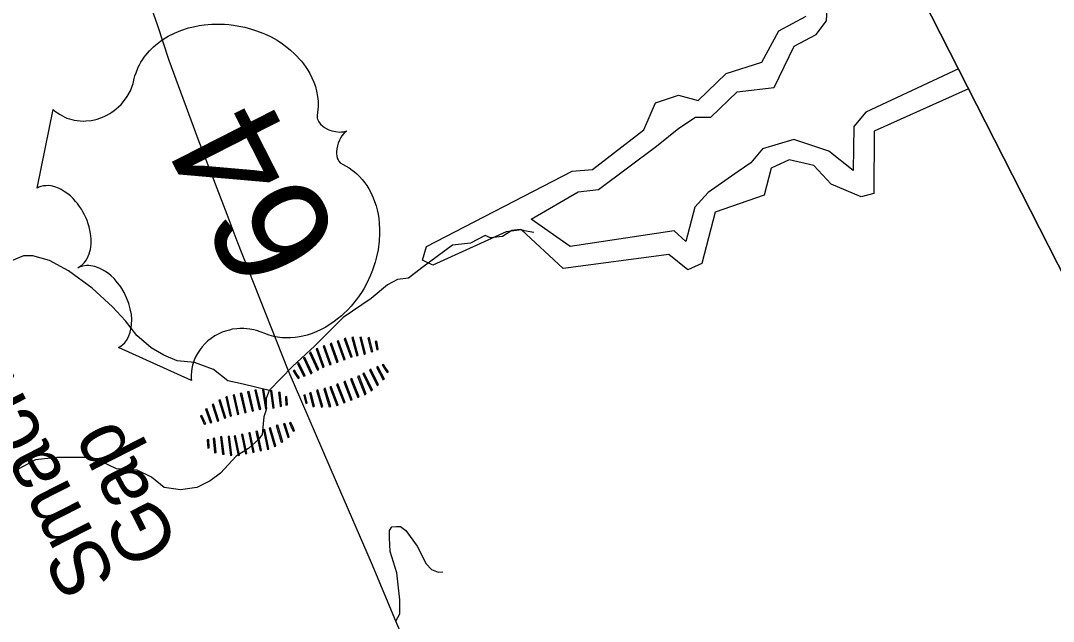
# Model space of a CAD drawing. Extents: x 558484 to 564063, y 513718 to 518374.
# Drawn here: x 559460.3 to 559521.9, y 515130.7 to 515166.6 of the extents above; entities that cross this region are included whole.
import ezdxf

# ---------------------------------------------------------------- set-up
doc = ezdxf.new("R2010")
doc.units = 0
doc.layers.add('Default', color=7, linetype='Continuous')

msp = doc.modelspace()

# ---------------------------------------------------------------- linework, layer by layer
at = {"layer": 'Default'}
for p, q in [((559470.585, 515166.219), (559470.927, 515166.283)), ((559470.927, 515166.283), (559471.228, 515166.33)), ((559471.228, 515166.33), (559471.685, 515166.371)), ((559471.685, 515166.371), (559472.029, 515166.376)), ((559472.029, 515166.376), (559472.441, 515166.365)), ((559472.441, 515166.365), (559472.697, 515166.345)), ((559472.697, 515166.345), (559472.976, 515166.311)), ((559472.976, 515166.311), (559473.306, 515166.258)), ((559469.073, 515165.643), (559469.458, 515165.841)), ((559469.458, 515165.841), (559469.839, 515165.998)), ((559469.839, 515165.998), (559470.301, 515166.146)), ((559470.301, 515166.146), (559470.585, 515166.219)), ((559473.306, 515166.258), (559473.665, 515166.184)), ((559473.665, 515166.184), (559474.06, 515166.076)), ((559474.06, 515166.076), (559474.36, 515165.978)), ((559474.36, 515165.978), (559474.724, 515165.837)), ((559474.724, 515165.837), (559474.934, 515165.746)), ((559474.934, 515165.746), (559475.218, 515165.608)), ((559468.197, 515165.008), (559468.322, 515165.122)), ((559468.322, 515165.122), (559468.618, 515165.35)), ((559468.618, 515165.35), (559468.767, 515165.456)), ((559468.767, 515165.456), (559469.073, 515165.643)), ((559475.218, 515165.608), (559475.578, 515165.405)), ((559475.578, 515165.405), (559475.908, 515165.191)), ((559475.908, 515165.191), (559476.171, 515165.001)), ((559467.645, 515164.393), (559467.737, 515164.519)), ((559467.737, 515164.519), (559467.963, 515164.781)), ((559467.963, 515164.781), (559468.197, 515165.008)), ((559476.171, 515165.001), (559476.385, 515164.823)), ((559476.385, 515164.823), (559476.647, 515164.585)), ((559476.647, 515164.585), (559477.033, 515164.162)), ((559467.297, 515163.803), (559467.368, 515163.946)), ((559467.368, 515163.946), (559467.452, 515164.097)), ((559467.452, 515164.097), (559467.544, 515164.242)), ((559467.544, 515164.242), (559467.645, 515164.393)), ((559477.033, 515164.162), (559477.162, 515164.003)), ((559477.162, 515164.003), (559477.302, 515163.806)), ((559477.302, 515163.806), (559477.422, 515163.618)), ((559467.056, 515163.117), (559467.098, 515163.279)), ((559467.098, 515163.279), (559467.161, 515163.472)), ((559467.161, 515163.472), (559467.297, 515163.803)), ((559477.422, 515163.618), (559477.532, 515163.431)), ((559477.532, 515163.431), (559477.664, 515163.171)), ((559466.822, 515162.39), (559466.916, 515162.614)), ((559466.916, 515162.614), (559466.988, 515162.824)), ((559466.988, 515162.824), (559467.056, 515163.117)), ((559477.664, 515163.171), (559477.776, 515162.904)), ((559477.776, 515162.904), (559477.865, 515162.642)), ((559477.865, 515162.642), (559477.941, 515162.361)), ((559466.415, 515161.745), (559466.626, 515162.044)), ((559466.626, 515162.044), (559466.822, 515162.39)), ((559477.941, 515162.361), (559477.997, 515162.056)), ((559477.997, 515162.056), (559478.025, 515161.766)), ((559465.979, 515161.305), (559466.118, 515161.428)), ((559466.118, 515161.428), (559466.273, 515161.581)), ((559466.273, 515161.581), (559466.415, 515161.745)), ((559478.029, 515161.462), (559477.98, 515160.917)), ((559478.025, 515161.766), (559478.029, 515161.462)), ((559461.259, 515156.585), (559462.216, 515161.265)), ((559462.216, 515161.265), (559462.286, 515161.202)), ((559462.286, 515161.202), (559462.467, 515161.066)), ((559462.467, 515161.066), (559462.625, 515160.965)), ((559462.625, 515160.965), (559462.903, 515160.818)), ((559462.903, 515160.818), (559463.041, 515160.765)), ((559463.041, 515160.765), (559463.184, 515160.714)), ((559464.845, 515160.701), (559465.163, 515160.813)), ((559465.163, 515160.813), (559465.309, 515160.875)), ((559465.309, 515160.875), (559465.449, 515160.946)), ((559465.449, 515160.946), (559465.592, 515161.029)), ((559465.592, 515161.029), (559465.727, 515161.115)), ((559465.727, 515161.115), (559465.862, 515161.216)), ((559465.862, 515161.216), (559465.979, 515161.305)), ((559477.98, 515160.917), (559477.977, 515160.766)), ((559477.977, 515160.766), (559477.993, 515160.691)), ((559463.184, 515160.714), (559463.328, 515160.674)), ((559463.328, 515160.674), (559463.461, 515160.641)), ((559463.461, 515160.641), (559463.644, 515160.613)), ((559463.644, 515160.613), (559463.822, 515160.594)), ((559463.822, 515160.594), (559464.012, 515160.585)), ((559464.012, 515160.585), (559464.172, 515160.588)), ((559464.172, 515160.588), (559464.492, 515160.622)), ((559464.492, 515160.622), (559464.686, 515160.659)), ((559464.686, 515160.659), (559464.845, 515160.701)), ((559477.993, 515160.691), (559478.067, 515160.527)), ((559478.067, 515160.527), (559478.174, 515160.394)), ((559478.174, 515160.394), (559478.313, 515160.271)), ((559478.313, 515160.271), (559478.41, 515160.204)), ((559478.41, 515160.204), (559478.553, 515160.122)), ((559478.553, 515160.122), (559478.676, 515160.066)), ((559478.676, 515160.066), (559478.842, 515160.007)), ((559478.842, 515160.007), (559478.973, 515159.974)), ((559478.973, 515159.974), (559479.074, 515159.95)), ((559479.074, 515159.95), (559479.316, 515159.928)), ((559479.372, 515159.57), (559479.305, 515159.443)), ((559479.316, 515159.928), (559479.423, 515159.93)), ((559479.454, 515159.701), (559479.372, 515159.57)), ((559479.423, 515159.93), (559479.558, 515159.944)), ((559479.56, 515159.832), (559479.454, 515159.701)), ((559479.558, 515159.944), (559479.742, 515159.99)), ((559479.742, 515159.99), (559479.56, 515159.832)), ((559479.145, 515158.926), (559479.132, 515158.751)), ((559479.183, 515159.104), (559479.145, 515158.926)), ((559479.23, 515159.259), (559479.183, 515159.104)), ((559479.305, 515159.443), (559479.23, 515159.259)), ((559479.132, 515158.751), (559479.132, 515158.616)), ((559479.132, 515158.616), (559479.144, 515158.498)), ((559479.144, 515158.498), (559479.176, 515158.363)), ((559479.176, 515158.363), (559479.218, 515158.261)), ((559479.218, 515158.261), (559479.261, 515158.181)), ((559479.261, 515158.181), (559479.343, 515158.083)), ((559479.343, 515158.083), (559479.528, 515157.988)), ((559479.528, 515157.988), (559479.699, 515157.895)), ((559479.699, 515157.895), (559479.875, 515157.789)), ((559479.875, 515157.789), (559480.067, 515157.654)), ((559480.067, 515157.654), (559480.199, 515157.551)), ((559480.199, 515157.551), (559480.344, 515157.422)), ((559480.344, 515157.422), (559480.503, 515157.265)), ((559480.503, 515157.265), (559480.66, 515157.087)), ((559480.66, 515157.087), (559480.809, 515156.898)), ((559461.36, 515156.632), (559461.259, 515156.585)), ((559461.484, 515156.675), (559461.36, 515156.632)), ((559461.634, 515156.711), (559461.484, 515156.675)), ((559461.787, 515156.722), (559461.634, 515156.711)), ((559461.936, 515156.726), (559461.787, 515156.722)), ((559462.093, 515156.705), (559461.936, 515156.726)), ((559462.323, 515156.648), (559462.093, 515156.705)), ((559462.531, 515156.571), (559462.323, 515156.648)), ((559462.691, 515156.499), (559462.531, 515156.571)), ((559462.881, 515156.385), (559462.691, 515156.499)), ((559480.809, 515156.898), (559480.932, 515156.728)), ((559480.932, 515156.728), (559481.051, 515156.539)), ((559481.051, 515156.539), (559481.148, 515156.363)), ((559463.094, 515156.233), (559462.881, 515156.385)), ((559463.244, 515156.109), (559463.094, 515156.233)), ((559463.401, 515155.961), (559463.244, 515156.109)), ((559463.556, 515155.788), (559463.401, 515155.961)), ((559481.148, 515156.363), (559481.241, 515156.175)), ((559481.241, 515156.175), (559481.317, 515155.993)), ((559481.317, 515155.993), (559481.402, 515155.781)), ((559463.667, 515155.653), (559463.556, 515155.788)), ((559463.794, 515155.481), (559463.667, 515155.653)), ((559463.901, 515155.32), (559463.794, 515155.481)), ((559463.996, 515155.157), (559463.901, 515155.32)), ((559481.402, 515155.781), (559481.493, 515155.511)), ((559481.493, 515155.511), (559481.552, 515155.278)), ((559481.552, 515155.278), (559481.605, 515155.028)), ((559464.09, 515154.977), (559463.996, 515155.157)), ((559464.161, 515154.828), (559464.09, 515154.977)), ((559464.24, 515154.64), (559464.161, 515154.828)), ((559464.304, 515154.45), (559464.24, 515154.64)), ((559481.605, 515155.028), (559481.649, 515154.766)), ((559481.649, 515154.766), (559481.68, 515154.477)), ((559464.363, 515154.262), (559464.304, 515154.45)), ((559464.411, 515154.066), (559464.363, 515154.262)), ((559464.445, 515153.871), (559464.411, 515154.066)), ((559481.68, 515154.477), (559481.702, 515154.107)), ((559481.702, 515154.107), (559481.701, 515153.841)), ((559464.466, 515153.713), (559464.445, 515153.871)), ((559464.475, 515153.554), (559464.466, 515153.713)), ((559464.476, 515153.222), (559464.475, 515153.554)), ((559481.68, 515153.412), (559481.608, 515152.885)), ((559481.701, 515153.841), (559481.68, 515153.412)), ((559464.371, 515152.66), (559464.41, 515152.797)), ((559464.41, 515152.797), (559464.436, 515152.916)), ((559464.436, 515152.916), (559464.476, 515153.222)), ((559481.608, 515152.885), (559481.52, 515152.47)), ((559464.007, 515152.051), (559464.087, 515152.141)), ((559464.087, 515152.141), (559464.193, 515152.284)), ((559464.193, 515152.284), (559464.271, 515152.423)), ((559464.271, 515152.423), (559464.371, 515152.66)), ((559481.435, 515152.155), (559481.273, 515151.675)), ((559481.52, 515152.47), (559481.435, 515152.155)), ((559463.688, 515151.822), (559463.837, 515151.912)), ((559463.88, 515151.902), (559463.688, 515151.822)), ((559463.837, 515151.912), (559463.926, 515151.977)), ((559463.978, 515151.927), (559463.88, 515151.902)), ((559463.926, 515151.977), (559464.007, 515152.051)), ((559464.215, 515151.959), (559463.978, 515151.927)), ((559464.335, 515151.956), (559464.215, 515151.959)), ((559464.463, 515151.947), (559464.335, 515151.956)), ((559464.71, 515151.896), (559464.463, 515151.947)), ((559464.969, 515151.805), (559464.71, 515151.896)), ((559465.124, 515151.726), (559464.969, 515151.805)), ((559465.307, 515151.619), (559465.124, 515151.726)), ((559465.514, 515151.475), (559465.307, 515151.619)), ((559481.273, 515151.675), (559481.157, 515151.381)), ((559465.681, 515151.332), (559465.514, 515151.475)), ((559465.847, 515151.171), (559465.681, 515151.332)), ((559465.982, 515151.019), (559465.847, 515151.171)), ((559466.247, 515150.679), (559465.982, 515151.019)), ((559480.928, 515150.897), (559480.75, 515150.571)), ((559481.157, 515151.381), (559480.928, 515150.897)), ((559466.446, 515150.349), (559466.247, 515150.679)), ((559466.602, 515150.03), (559466.446, 515150.349)), ((559480.611, 515150.348), (559480.378, 515150.007)), ((559480.75, 515150.571), (559480.611, 515150.348)), ((559466.729, 515149.691), (559466.602, 515150.03)), ((559466.82, 515149.368), (559466.729, 515149.691)), ((559480.225, 515149.806), (559479.994, 515149.53)), ((559480.378, 515150.007), (559480.225, 515149.806)), ((559466.883, 515149.039), (559466.82, 515149.368)), ((559466.906, 515148.726), (559466.883, 515149.039)), ((559479.561, 515149.081), (559479.421, 515148.953)), ((559479.775, 515149.294), (559479.561, 515149.081)), ((559479.994, 515149.53), (559479.775, 515149.294)), ((559466.881, 515148.259), (559466.9, 515148.437)), ((559466.9, 515148.437), (559466.906, 515148.726)), ((559478.726, 515148.425), (559478.443, 515148.255)), ((559478.984, 515148.604), (559478.726, 515148.425)), ((559479.167, 515148.745), (559478.984, 515148.604)), ((559479.421, 515148.953), (559479.167, 515148.745)), ((559466.722, 515147.706), (559466.819, 515147.978)), ((559466.819, 515147.978), (559466.881, 515148.259)), ((559472.061, 515147.856), (559471.868, 515147.75)), ((559472.304, 515147.968), (559472.061, 515147.856)), ((559472.508, 515148.039), (559472.304, 515147.968)), ((559472.731, 515148.103), (559472.508, 515148.039)), ((559472.908, 515148.145), (559472.731, 515148.103)), ((559473.171, 515148.182), (559472.908, 515148.145)), ((559473.348, 515148.196), (559473.171, 515148.182)), ((559473.594, 515148.193), (559473.348, 515148.196)), ((559473.765, 515148.184), (559473.594, 515148.193)), ((559473.962, 515148.163), (559473.765, 515148.184)), ((559474.183, 515148.123), (559473.962, 515148.163)), ((559474.348, 515148.081), (559474.183, 515148.123)), ((559474.635, 515147.984), (559474.348, 515148.081)), ((559474.849, 515147.889), (559474.635, 515147.984)), ((559475.108, 515147.798), (559474.849, 515147.889)), ((559475.38, 515147.722), (559475.108, 515147.798)), ((559477.373, 515147.802), (559477.108, 515147.734)), ((559477.673, 515147.899), (559477.373, 515147.802)), ((559477.948, 515148.007), (559477.673, 515147.899)), ((559478.176, 515148.114), (559477.948, 515148.007)), ((559478.443, 515148.255), (559478.176, 515148.114)), ((559466.255, 515147.139), (559466.401, 515147.256)), ((559466.401, 515147.256), (559466.473, 515147.325)), ((559466.473, 515147.325), (559466.595, 515147.483)), ((559466.595, 515147.483), (559466.722, 515147.706)), ((559471.286, 515147.302), (559471.107, 515147.107)), ((559471.452, 515147.452), (559471.286, 515147.302)), ((559471.65, 515147.607), (559471.452, 515147.452)), ((559471.868, 515147.75), (559471.65, 515147.607)), ((559475.613, 515147.677), (559475.38, 515147.722)), ((559475.877, 515147.646), (559475.613, 515147.677)), ((559476.114, 515147.634), (559475.877, 515147.646)), ((559476.39, 515147.636), (559476.114, 515147.634)), ((559476.668, 515147.66), (559476.39, 515147.636)), ((559476.912, 515147.695), (559476.668, 515147.66)), ((559477.108, 515147.734), (559476.912, 515147.695)), ((559466.121, 515147.061), (559466.255, 515147.139)), ((559470.469, 515145.081), (559466.121, 515147.061)), ((559470.831, 515146.71), (559470.701, 515146.465)), ((559470.985, 515146.949), (559470.831, 515146.71)), ((559471.107, 515147.107), (559470.985, 515146.949)), ((559470.538, 515146.012), (559470.5, 515145.814)), ((559470.61, 515146.235), (559470.538, 515146.012)), ((559470.701, 515146.465), (559470.61, 515146.235)), ((559470.472, 515145.631), (559470.456, 515145.409)), ((559470.456, 515145.409), (559470.458, 515145.205)), ((559470.5, 515145.814), (559470.472, 515145.631)), ((559470.458, 515145.205), (559470.469, 515145.081))]:
    msp.add_line(p, q, dxfattribs=at)
for points in [[(559691.675, 514819.143), (559493.11, 515209.152), (559540.175, 515233.114), (559738.739, 514843.105)], [(559363.742, 514652.183), (559165.177, 515042.192), (559493.11, 515209.152), (559691.675, 514819.143)], [(559363.742, 514652.183), (559165.177, 515042.192), (559493.11, 515209.152), (559691.675, 514819.143)], [(559479.146, 515146.169), (559479.229, 515146.199), (559478.827, 515147.31), (559478.745, 515147.28)], [(559479.57, 515146.323), (559479.653, 515146.352), (559479.251, 515147.463), (559479.169, 515147.434)], [(559479.985, 515146.473), (559480.07, 515146.503), (559479.668, 515147.614), (559479.584, 515147.584)], [(559480.338, 515146.561), (559480.421, 515146.591), (559480.122, 515147.684), (559480.037, 515147.653)], [(559480.781, 515146.643), (559480.864, 515146.673), (559480.593, 515147.681), (559480.51, 515147.651)], [(559481.094, 515147.62), (559481.082, 515147.654), (559480.998, 515147.624), (559481.192, 515146.831), (559481.204, 515146.796), (559481.287, 515146.826)], [(559481.537, 515146.916), (559481.619, 515146.946), (559481.526, 515147.445), (559481.444, 515147.416)], [(559477.985, 515145.711), (559478.067, 515145.741), (559477.601, 515146.773), (559477.519, 515146.743)], [(559478.305, 515145.866), (559478.39, 515145.896), (559477.989, 515147.007), (559477.904, 515146.977)], [(559478.729, 515146.019), (559478.813, 515146.049), (559478.412, 515147.16), (559478.328, 515147.13)], [(559476.894, 515146.103), (559476.882, 515146.137), (559476.798, 515146.107), (559477.158, 515145.373), (559477.17, 515145.339), (559477.254, 515145.369)], [(559477.587, 515145.489), (559477.669, 515145.519), (559477.233, 515146.467), (559477.15, 515146.437)], [(559481.929, 515146.053), (559481.847, 515146.021), (559481.997, 515145.797), (559482.15, 515145.569), (559482.232, 515145.601), (559482.08, 515145.829)], [(559476.83, 515145.216), (559476.913, 515145.246), (559476.768, 515145.474), (559476.621, 515145.705), (559476.538, 515145.676), (559476.684, 515145.444)], [(559480.47, 515145.369), (559480.386, 515145.336), (559480.813, 515144.235), (559480.898, 515144.268)], [(559480.787, 515145.531), (559480.705, 515145.499), (559481.195, 515144.478), (559481.277, 515144.51)], [(559481.179, 515145.762), (559481.097, 515145.73), (559481.556, 515144.793), (559481.638, 515144.825)], [(559481.886, 515145.165), (559481.899, 515145.131), (559481.982, 515145.164), (559481.605, 515145.888), (559481.592, 515145.922), (559481.509, 515145.89)], [(559478.805, 515144.722), (559478.721, 515144.69), (559479.149, 515143.588), (559479.232, 515143.621)], [(559479.216, 515144.882), (559479.135, 515144.85), (559479.562, 515143.749), (559479.644, 515143.781)], [(559479.637, 515145.045), (559479.555, 515145.013), (559479.982, 515143.912), (559480.064, 515143.944)], [(559480.05, 515145.206), (559479.966, 515145.173), (559480.394, 515144.072), (559480.477, 515144.104)], [(559472.779, 515142.953), (559472.867, 515142.973), (559472.6, 515144.124), (559472.512, 515144.103)], [(559473.218, 515143.055), (559473.305, 515143.075), (559473.038, 515144.225), (559472.951, 515144.205)], [(559473.65, 515143.155), (559473.736, 515143.175), (559473.469, 515144.325), (559473.383, 515144.305)], [(559474.089, 515143.257), (559474.175, 515143.276), (559473.908, 515144.427), (559473.822, 515144.407)], [(559474.519, 515143.356), (559474.607, 515143.377), (559474.34, 515144.527), (559474.252, 515144.507)], [(559474.88, 515143.403), (559474.966, 515143.422), (559474.799, 515144.543), (559474.711, 515144.522)], [(559475.33, 515143.432), (559475.415, 515143.451), (559475.266, 515144.484), (559475.18, 515144.464)], [(559475.756, 515144.364), (559475.748, 515144.4), (559475.662, 515144.38), (559475.759, 515143.569), (559475.768, 515143.533), (559475.853, 515143.553)], [(559476.112, 515143.613), (559476.198, 515143.633), (559476.165, 515144.14), (559476.079, 515144.12)], [(559477.264, 515144.241), (559477.182, 515144.21), (559477.287, 515143.713), (559477.369, 515143.745)], [(559477.723, 515143.549), (559477.737, 515143.515), (559477.819, 515143.547), (559477.607, 515144.335), (559477.594, 515144.37), (559477.512, 515144.338)], [(559478.013, 515144.532), (559477.932, 515144.501), (559478.226, 515143.5), (559478.308, 515143.532)], [(559478.454, 515144.625), (559478.372, 515144.593), (559478.697, 515143.508), (559478.781, 515143.541)], [(559472.021, 515142.664), (559472.107, 515142.684), (559471.786, 515143.677), (559471.7, 515143.657)], [(559472.443, 515142.837), (559472.528, 515142.857), (559472.188, 515143.937), (559472.102, 515143.917)], [(559471.237, 515142.482), (559471.324, 515142.502), (559471.206, 515142.746), (559471.088, 515142.993), (559471.002, 515142.973), (559471.12, 515142.726)], [(559471.406, 515143.355), (559471.398, 515143.391), (559471.311, 515143.37), (559471.582, 515142.6), (559471.59, 515142.564), (559471.676, 515142.584)], [(559475.19, 515142.261), (559475.104, 515142.243), (559475.419, 515141.155), (559475.505, 515141.173)], [(559475.616, 515142.424), (559475.53, 515142.406), (559475.827, 515141.406), (559475.914, 515141.424)], [(559476.214, 515141.718), (559476.221, 515141.683), (559476.309, 515141.701), (559476.057, 515142.478), (559476.049, 515142.513), (559475.963, 515142.495)], [(559476.404, 515142.587), (559476.317, 515142.569), (559476.429, 515142.323), (559476.541, 515142.073), (559476.627, 515142.09), (559476.516, 515142.341)], [(559471.841, 515140.813), (559471.849, 515140.777), (559471.936, 515140.795), (559471.857, 515141.608), (559471.85, 515141.644), (559471.764, 515141.626)], [(559472.29, 515141.735), (559472.204, 515141.717), (559472.329, 515140.682), (559472.415, 515140.699)], [(559472.74, 515141.754), (559472.654, 515141.736), (559472.794, 515140.612), (559472.883, 515140.63)], [(559473.102, 515141.791), (559473.014, 515141.773), (559473.254, 515140.616), (559473.341, 515140.634)], [(559473.535, 515141.881), (559473.449, 515141.863), (559473.688, 515140.706), (559473.774, 515140.724)], [(559473.976, 515141.972), (559473.89, 515141.954), (559474.129, 515140.798), (559474.215, 515140.815)], [(559474.41, 515142.062), (559474.322, 515142.044), (559474.562, 515140.887), (559474.649, 515140.905)], [(559474.851, 515142.153), (559474.763, 515142.135), (559475.002, 515140.978), (559475.091, 515140.997)], [(559471.503, 515141.572), (559471.417, 515141.555), (559471.438, 515141.047), (559471.524, 515141.065)]]:
    msp.add_lwpolyline(points, close=True, dxfattribs=at)
for points in [[(559482.668, 515130.71), (559481.214, 515134.192), (559479.119, 515139.022), (559476.235, 515145.707), (559473.191, 515153.418), (559472.592, 515154.993), (559470.876, 515159.499), (559469.148, 515164.201), (559468.441, 515166.328), (559467.464, 515169.099), (559466.792, 515171.157), (559464.653, 515177.718), (559463.178, 515182.197), (559462.177, 515186.028), (559461.567, 515187.933)], [(559516.256, 515163.692), (559510.712, 515161.116), (559510.007, 515160.258), (559509.961, 515157.623), (559508.513, 515158.784), (559506.414, 515159.477), (559504.549, 515158.918), (559503.849, 515158.086), (559503.102, 515157.565), (559501.313, 515156.315), (559500.517, 515155.449), (559499.985, 515153.391), (559499.284, 515154.035), (559493.074, 515153.088), (559490.74, 515154.731), (559493.558, 515156.359), (559494.765, 515156.497), (559498.229, 515159.079), (559499.554, 515160.162), (559500.551, 515160.814), (559501.467, 515160.816), (559503.041, 515162.319), (559505.24, 515162.597), (559506.452, 515165.053), (559507.749, 515165.751), (559508.374, 515166.57), (559508.441, 515167.674)], [(559516.857, 515162.51), (559511.225, 515159.976), (559511.203, 515156.256), (559510.444, 515156.059), (559508.652, 515156.821), (559507.607, 515157.924), (559506.136, 515158.258), (559505.06, 515157.777), (559504.647, 515156.161), (559501.728, 515155.136), (559500.934, 515152.069), (559500.094, 515151.691), (559498.964, 515152.61), (559492.654, 515151.771), (559490.173, 515154.078), (559489.263, 515153.958), (559484.868, 515151.981), (559484.268, 515152.28), (559484.498, 515153.099), (559493.202, 515157.582), (559494.4, 515157.692), (559497.463, 515160.067), (559498.168, 515161.667), (559499.533, 515162.139), (559500.715, 515161.814), (559502.385, 515163.423), (559504.509, 515164.092), (559505.531, 515165.978), (559507.157, 515166.852)], [(559490.901, 515153.922), (559490.347, 515154.031), (559490.091, 515154.114), (559489.595, 515154.039), (559489.031, 515153.681), (559488.322, 515153.605), (559487.995, 515153.758), (559487.133, 515153.284), (559486.056, 515153.162), (559484.216, 515151.816), (559483.426, 515151.201), (559482.76, 515151.111), (559482.167, 515150.808), (559481.194, 515149.993), (559479.529, 515148.861), (559477.832, 515147.161), (559476.508, 515145.918), (559475.804, 515145.204), (559475.1, 515144.49)], [(559475.1, 515144.49), (559473.559, 515144.861), (559472.636, 515145.067), (559471.795, 515145.741), (559470.657, 515146.158), (559469.607, 515146.264), (559468.825, 515146.612), (559468.07, 515147.046), (559467.2, 515147.776), (559466.542, 515148.65), (559465.756, 515149.495), (559464.55, 515150.606), (559463.139, 515151.63), (559462, 515152.26), (559461.005, 515152.536), (559460.438, 515152.532), (559459.731, 515152.243)], [(559475.1, 515144.49), (559474.919, 515144.007), (559474.938, 515143.341), (559474.799, 515142.914), (559474.693, 515141.865), (559474.483, 515141.579), (559473.877, 515141.022), (559473.143, 515140.577), (559472.2, 515139.564), (559471.579, 515139.105), (559470.788, 515138.703), (559469.825, 515138.568), (559468.831, 515138.702), (559468.09, 515139.32), (559467.236, 515139.739), (559465.987, 515139.815), (559465.048, 515140.262), (559464.224, 515140.482), (559462.438, 515140.497), (559461.163, 515140.346), (559457.97, 515138.649)], [(559482.668, 515130.71), (559482.908, 515131.15), (559482.913, 515131.992), (559482.729, 515133.604), (559482.339, 515134.881), (559482.288, 515135.664), (559482.284, 515136.125), (559482.433, 515136.346), (559482.709, 515136.371), (559482.94, 515136.372), (559483.264, 515136.133), (559483.94, 515135.204), (559484.478, 515134.148), (559484.803, 515133.793), (559485.196, 515133.646), (559485.473, 515133.671)], [(559505.859, 515053.881), (559505.297, 515056.524), (559504.874, 515058.408), (559504.423, 515061.774), (559504.212, 515065.153), (559504.22, 515067.338), (559504.243, 515069.078), (559504.235, 515071.071), (559504.106, 515073.917), (559503.698, 515077.151), (559503.391, 515078.926), (559502.998, 515080.648), (559502.52, 515082.467), (559500.892, 515087.193), (559499.416, 515090.742), (559497.493, 515095.515), (559495.386, 515100.526), (559493.145, 515105.762), (559491.266, 515109.985), (559488.761, 515115.971), (559485.916, 515123.138), (559482.668, 515130.71)]]:
    msp.add_lwpolyline(points, dxfattribs=at)

# ---------------------------------------------------------------- texts
for s, height, p in [('64', 6.8555, (559479.514, 515153.203)), ('Smackass', 3.4375, (559466.059, 515133.261)), ('Gap', 3.4375, (559469.807, 515135.17))]:
    msp.add_text(s, height=height, rotation=116.98193, dxfattribs=at).set_placement(p)

doc.saveas('drawing.dxf')
